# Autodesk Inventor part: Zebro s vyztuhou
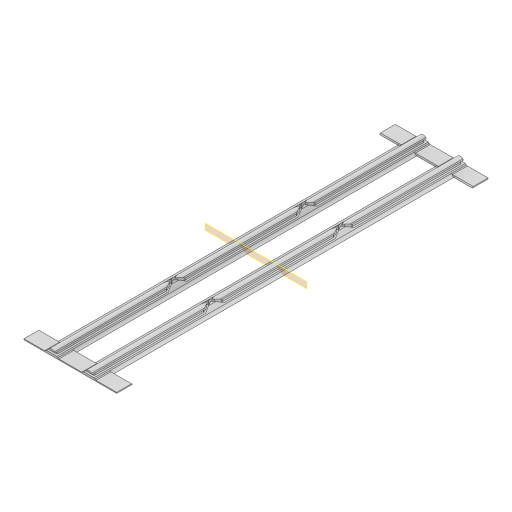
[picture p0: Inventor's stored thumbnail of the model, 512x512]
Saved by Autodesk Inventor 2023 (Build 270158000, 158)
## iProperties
Created: 2025-03
Part Number: Zebro s vyztuhou
Material: Všeobecné
Document SubType Name: Modeling
Designer: tomik
Density: 1 g/cm^3
Appearance: Výchozí
Author: tomik
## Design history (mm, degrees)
sketch "Náčrt1"
  geometry: L1 (0, 0)-(0, 11.016); L2 (0, 0)-(4, 0); L3 (0, 4)-(4, 0); L4 (0, 4)-(-4, 0); L5 (0, 0)-(-4, 0)
  constraints: 10 end point, 1 horizontal, 1 point on line, 1 symmetric about line, 1 vertical
  dimensions: "d0" = 4 distance of L1.start L2.end; "d1" = 4 distance from line of L3.start L2
extrude "Vysunutí1" new body sketch "Náčrt1" distance "d2" = 200; taper "d3" = 0 deg
sketch "Náčrt2"
  geometry: L1 (0, 0)-(9.652, 0); L2 (4, 0)-(0, 4) reference; L3 (4, 0)-(5.036, 0); A1 r 2.5 centre (5.036, 2.5) between (3.268, 0.732) and (5.036, 0)
  constraints: 4 end point, 3 tangent, 2 point on circle, 2 point on line, 1 centre point, 1 collinear, 1 horizontal
  dimensions: "d4" = 5 diameter of A1
extrude "Vysunutí2" join sketch "Náčrt2" distance "d5" = 200; taper "d6" = 0 deg
fillet "Zaoblení1" dims "d7" = 2
mirror "Zrcadlit1"
sketch "Náčrt3"
  geometry: L1 (-2.8, 1.2)-(-1.8, 1.2); L2 (-1.8, 1.2)-(-1.8, 2.2); L3 (-1.8, 2.2)-(-2.8, 2.2); L4 (-2.8, 2.2)-(-2.8, 1.2); L5 (0, 0)-(-6.364, 0); L6 (0, 0)-(0, 0.195); L7 (0, 0)-(0, 0.195); L8 (0, 0)-(0, 4.884); L9 (-1.8, 1.2)-(0, 1.2)
  constraints: 18 end point, 2 horizontal, 2 parallel, 2 perpendicular, 1 collinear, 1 point on line, 1 vertical
  dimensions: "d8" = 1.2 distance between parallel lines of L1 L5; "d9" = 1.8 distance between parallel lines of L2 L8; "d10" = 1 distance between parallel lines of L2 L4; "d11" = 1 distance between parallel lines of L3 L1
extrude "Vysunutí3" cut sketch "Náčrt3" distance "d12" = 60; taper "d13" = 0 deg
sketch "Náčrt4"
  geometry: L1 (1.8, 2.2)-(1.8, 1.2) reference; L2 (1.8, 1.2)-(2.8, 1.2) reference; L3 (1.414, 2.586)-(3.268, 0.732) reference; 1 further point
extrude "Vysunutí4" cut sketch "Náčrt4" distance "d14" = 60; taper "d15" = 0 deg
node "Pracovní rovina1"
sketch "Náčrt7"
  geometry: L1 (2.8, 1.2)-(1.8, 2.2) reference; L2 (1.8, 2.2)-(1.8, 1.2) reference; L3 (1.8, 1.2)-(2.8, 1.2) reference; 1 further point
extrude "Vysunutí6" cut sketch "Náčrt7" distance "d19" = 60; taper "d20" = 0 deg
mirror "Zrcadlit2"
node "Pracovní rovina3"
sketch "Náčrt8"
  geometry: L1 (-2.236, 60)-(-3.236, 60) reference; L2 (2.014, 70)-(-12.085, 70) reference; L3 (-3.236, 60)-(-3.236, 0) reference; L4 (-7.836, 70)-(-6.836, 70) reference; L5 (-3.236, 60)-(-7.836, 70); L6 (-2.236, 0)-(-2.236, 60) reference; L7 (-6.836, 70)-(-2.236, 60); 1 further point
  constraints: 4 end point
extrude "Vysunutí7" cut sketch "Náčrt8" stored distance "d22" = 60; taper "d23" = 0 deg
mirror "Zrcadlit3"
node "Pracovní rovina4"
mirror "Zrcadlit4"
fillet "Zaoblení2" dims "d25" = 0.5
sketch "Náčrt9"
  geometry: L1 (60, -1)-(0, -1) reference; L2 (59.891, 0)-(0, 0) reference; L3 (0, -1)-(1, -1); L4 (1, -1)-(1, 0); L5 (1, 0)-(0, 0); L6 (0, 0)-(0, -1); 3 further points
  constraints: 8 end point, 2 parallel, 1 horizontal, 1 perpendicular, 1 point on line
  dimensions: "d26" = 1 distance between parallel lines of L6 L4
extrude "Vysunutí8" cut sketch "Náčrt9" stored distance "d27" = 10; taper "d28" = 0 deg
fillet "Zaoblení3" dims "d29" = 0.5
mirror "Zrcadlit5"
pattern_linear "Obdélníkové pole1"
sketch "Náčrt10"
  geometry: L1 (0, -200)-(10.071, -200) reference; L2 (5, -200)-(25, -200); L3 (25, -200)-(25, -191.5); L4 (25, -191.5)-(5, -191.5); L5 (5, -191.5)-(5, -200); L6 (0, 0)-(0, -200) reference; 3 further points
  constraints: 8 end point, 2 parallel, 1 collinear, 1 horizontal, 1 perpendicular
  dimensions: "d36" = 5 distance between parallel lines of L6 L5; "d37" = 25 distance between parallel lines of L6 L3; "d38" = 8.5 distance between parallel lines of L2 L4
extrude "Vysunutí9" join sketch "Náčrt10" distance "d39" = 0.5; taper "d40" = 0 deg
fillet "Zaoblení4" dims "d41" = 0.8
feature "Kombinovat1"
  node "Těleso2"
fillet "Zaoblení5" dims "d42" = 0.8
chamfer "Zkosení1" distance "d43" = 0.5; stored, may be unused: second distance "d44" = 2, angle "d45" = 45 deg
node "Pracovní rovina5"
mirror "Zrcadlit6"
sketch "Náčrt11"
  geometry: L1 (22.236, -200)-(27.836, -200) reference; L2 (25.036, -200)-(40.036, -200); L3 (21.204, -200)-(8.867, -200) reference; L4 (40.036, -200)-(40.036, -191.5); L5 (40.036, -191.5)-(25.036, -191.5); L6 (25.036, -191.5)-(25.036, -200); 2 further points
  constraints: 8 end point, 1 collinear, 1 horizontal, 1 midpoint, 1 perpendicular
  dimensions: "d47" = 15 distance of L2.start L2.end; "d48" = 8.5 distance of L2.end L4.end; "d49" = 15 distance of L4.end L5.end
extrude "Vysunutí10" join sketch "Náčrt11" distance "d50" = 0.5; taper "d51" = 0 deg
mirror "Zrcadlit7"
node "Pracovní rovina6"
mirror "Zrcadlit8"
fillet "Zaoblení6" dims "d53" = 0.8
chamfer "Zkosení2" distance "d54" = 0.5; stored, may be unused: second distance "d55" = 2, angle "d56" = 45 deg
node "Těleso1"
node "Pracovní rovina2"
feature "Pole Těleso1:1"
feature "Pole Těleso1:2"
node "Těleso3"
feature "Pole Těleso1:3"
node "Těleso4"
